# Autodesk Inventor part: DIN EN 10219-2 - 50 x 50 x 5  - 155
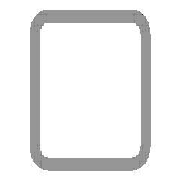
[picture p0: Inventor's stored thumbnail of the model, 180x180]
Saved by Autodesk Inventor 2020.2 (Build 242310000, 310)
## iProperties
_CCFamilyMember: 16
_CCFamilyDisplayName: DIN EN 10219-2 (Quadratisches Hohlprofil - Kaltgeformt) - Kaltgeformte, geschweißte Baustahl-Hohlprofile aus unlegiertem Feinkorn-Baustahl
_FrameMemberDoc: Frame Member File
_Version: 15.0.0
_GetPNFromCC: 1
IsCustomPart: 1
Created: 2019-11
Part Number: DIN EN 10219-2 - 50 x 50 x 5  - 155
Material: Stahl, weich
Description: Kaltgeformte, geschweißte Baustahl-Hohlprofile aus unlegiertem Feinkorn-Baustahl
Document SubType Name: Modeling
Standard: DIN
Designer: lutzd
Standard Revision: 2006-07
Standards Organization: DIN
Language: de-DE
Size Designation: 50 x 50 x 5
Categories: <MemberInstance><Categories><Category DisplayName="Profile" InternalName="089c4875-fa83-4c05-b084-43b9cc11f5ed" Mnemonic="GRDR"><CategoryParameter DisplayName="
Stock Number: 50 x 50 x 5
Mass: 1016.74 g
Surface Area: 534.796 cm^2
Volume: 129.521 cm^3
Density: 7.85 g/cm^3
Appearance: Semi-Polished(8)
G_W: 50,000 mm
G_H: 50,000 mm
Mass: 1,017 kg
VLT_Material: Stahl, weich
DocNumber: ADSK-014415
Folder: .
Dimensions: 50x50x155 mm
G_L: 155,000 mm
+A718D262-97A4-4385-A99A-9072C75C80CA+SCHNITTDETAIL2: Schnittwinkel 90,00 grd
Title: Profil-Bauteil
Author: lutzd
Revision Number: -
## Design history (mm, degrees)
node "Startebene"
node "Endebene"
sketch "Skizze"
  geometry: L1 (-25, -15)-(-25, 15); L2 (-15, 25)-(15, 25); L3 (25, 15)-(25, -15); L4 (15, -25)-(-15, -25); L5 (-15, 20)-(15, 20); L6 (20, 15)-(20, -15); L7 (15, -20)-(-15, -20); L8 (-20, -15)-(-20, 15); L9 (0, 37.899)-(0, -37.899) reference; L10 (-37.899, 0)-(37.899, 0) reference; A1 r 10 centre (-15, -15) between (-25, -15) and (-15, -25); A2 r 10 centre (-15, 15) between (-15, 25) and (-25, 15); A3 r 10 centre (15, 15) between (25, 15) and (15, 25); A4 r 10 centre (15, -15) between (15, -25) and (25, -15); A5 r 5 centre (-15, 15) between (-15, 20) and (-20, 15); A6 r 5 centre (15, 15) between (20, 15) and (15, 20); A7 r 5 centre (15, -15) between (15, -20) and (20, -15); A8 r 5 centre (-15, -15) between (-20, -15) and (-15, -20)
  constraints: 16 end point, 16 point on circle, 8 centre point, 8 tangent, 4 parallel, 3 equal radius, 2 perpendicular, 7 other
  dimensions: "d7" = 10 radius of A1 (= G_IR); "d10" = 50 distance between parallel lines of L2 L4 (= G_H); "d11" = 50 distance between parallel lines of L1 L3 (= G_W); "d12" = 5 distance between parallel lines of L3 L6 (= G_T); "d15" = 25 distance between parallel lines of L2 L10 (= 0.5 x d10); "d16" = 25 distance between parallel lines of L9 L3 (= 0.5 x d11)
extrude "Körper" new body sketch "Skizze" stored distance "d3" = 155 (= G_L); taper "d4" = 0 deg
node "Driven Length"
  sketch "Sketch3"
    geometry: L1 (0, 0)-(10, 0) reference
    constraints: 2 end point, 1 horizontal
  workplane "Work Plane3"
  sketch "Sketch4"
    geometry: L1 (-2, 0)-(12, 0) reference; L2 (-2, 155)-(12, 155) reference
    dimensions: "d18" = 155 distance between parallel lines of L1 L2 (derived)
workplane "Arbeitsebene5"
feature "Trennen2"
body "Solid1"
other parameters: "G_W" = 50 [user parameter; used in 1 equation term], "G_H" = 50 [user parameter; used in 1 equation term], "G_T" = 5 [user parameter; used in 1 equation term], "G_IR" = 10 [user parameter; used in 1 equation term], "G_L" = 155 (= d18) [user parameter; used in 1 equation term], "G_OFFSET_START" = 0 [user parameter; used in 1 equation term], "G_OFFSET_END" = 0 [user parameter; used in 1 equation term], "d13" = 0 (computed from G_OFFSET_START), "d14" = 155 (= G_OFFSET_END + B_L), "B_L" = 155 [user parameter; used in 1 equation term], "d17" = 90 deg
